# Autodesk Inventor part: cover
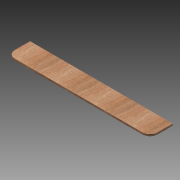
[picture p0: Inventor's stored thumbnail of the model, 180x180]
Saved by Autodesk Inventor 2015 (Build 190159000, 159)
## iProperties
Created: 2015-04
Part Number: cover
Material: Wood (Birch)
Document SubType Name: Modeling
Designer: sungeun
Density: 0.55 g/cm^3
Appearance: Birch - Natural Polished
Author: sungeun
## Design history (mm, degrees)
sketch "Sketch1"
  geometry: L1 (-470, 82)-(-470, 182); L2 (-470, 182)-(0, 182); L3 (0, 182)-(0, 72); L4 (470, 182)-(0, 182); L5 (470, 82)-(470, 182); L6 (-420, 32)-(420, 32); A1 r 50 centre (-420, 82) between (-470, 82) and (-420, 32); A2 r 50 centre (420, 82) between (420, 32) and (470, 82); 2 further points
  constraints: 12 end point, 4 point on circle, 4 tangent, 2 centre point, 2 horizontal, 2 point on line, 1 midpoint, 1 symmetric about line, 1 vertical
  dimensions: "d2" = 90 deg angle of L2 L1; "d8" = 470 distance of L1.end L2.end; "d21" = 50 radius of A1; "d22" = 50 radius of A2
extrude "Extrusion1" new body sketch "Sketch1" distance "d6" = 12 (= thickness); taper "d7" = 0 deg
body "Solid1"
other parameters: "thickness" = 12 [user parameter; used in 1 equation term]
